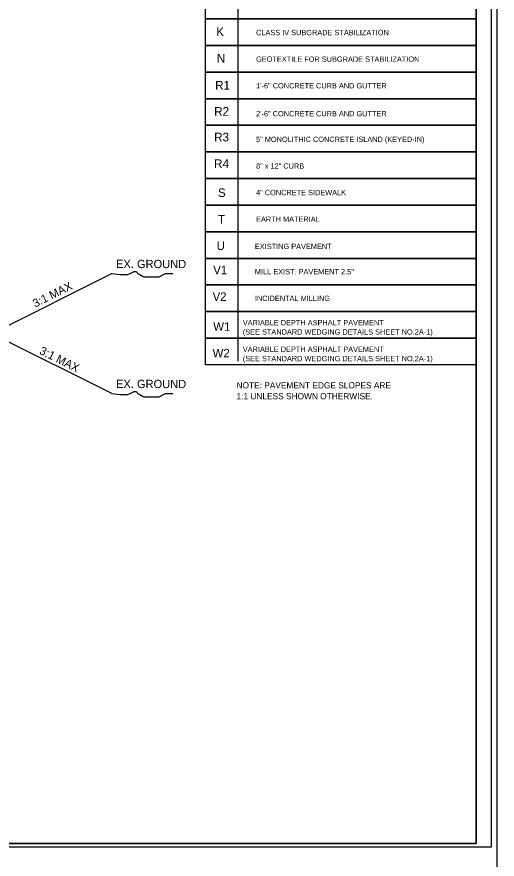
# Model space of a CAD drawing. Extents: x 2320980 to 2456309, y 595047 to 606177.
# Drawn here: x 2455968.3 to 2456045.5, y 596305.6 to 596440.9 of the extents above; entities that cross this region are included whole.
import ezdxf

# ---------------------------------------------------------------- set-up
doc = ezdxf.new("R2010")
doc.units = 0
for name, color, linetype in [('Old_Level_1', 7, 'Continuous'), ('Old_Level_21', 7, 'Continuous'), ('Prop Dimension', 7, 'Continuous'), ('Prop Pavement Schedule Description CELL', 7, 'Continuous'), ('Sheet Plan CELL', 7, 'Continuous'), ('Sheet Plot Border Inside CELL', 7, 'Continuous'), ('Sheet Plot Border Outside CELL', 7, 'Continuous'), ('Typical Slope Point Local CELL', 7, 'Continuous')]:
    doc.layers.add(name, color=color, linetype=linetype)

msp = doc.modelspace()

# ---------------------------------------------------------------- linework, layer by layer
at = {"layer": 'Prop Dimension'}
msp.add_line((2456003.83, 596479.09), (2456003.83, 596385.59), dxfattribs=at)
for points in [[(2455998.64, 596444.88), (2456042.11, 596444.88), (2456042.11, 596440.6), (2455998.64, 596440.6)], [(2455998.64, 596440.6), (2456042.11, 596440.6), (2456042.11, 596436.33), (2455998.64, 596436.33)], [(2455998.64, 596436.33), (2456042.11, 596436.33), (2456042.11, 596432.05), (2455998.64, 596432.05)], [(2455998.64, 596432.05), (2456042.11, 596432.05), (2456042.11, 596427.78), (2455998.64, 596427.78)], [(2455998.64, 596427.78), (2456042.11, 596427.78), (2456042.11, 596423.5), (2455998.64, 596423.5)], [(2455998.64, 596423.5), (2456042.11, 596423.5), (2456042.11, 596419.22), (2455998.64, 596419.22)], [(2455998.64, 596419.22), (2456042.11, 596419.22), (2456042.11, 596414.95), (2455998.64, 596414.95)], [(2455998.64, 596414.95), (2456042.11, 596414.95), (2456042.11, 596410.67), (2455998.64, 596410.67)], [(2455998.64, 596410.67), (2456042.11, 596410.67), (2456042.11, 596406.4), (2455998.64, 596406.4)], [(2455998.64, 596406.4), (2456042.11, 596406.4), (2456042.11, 596402.12), (2455998.64, 596402.12)], [(2455998.64, 596402.12), (2456042.11, 596402.12), (2456042.11, 596397.84), (2455998.64, 596397.84)], [(2455998.64, 596397.84), (2456042.11, 596397.84), (2456042.11, 596393.57), (2455998.64, 596393.57)], [(2455998.64, 596393.57), (2456042.11, 596393.57), (2456042.11, 596389.29), (2455998.64, 596389.29)], [(2455998.64, 596389.29), (2456042.11, 596389.29), (2456042.11, 596385.01), (2455998.64, 596385.01)]]:
    msp.add_lwpolyline(points, close=True, dxfattribs=at)
at = {"layer": 'Prop Pavement Schedule Description CELL'}
msp.add_line((2455998.64, 596385.01), (2455998.64, 596385.01), dxfattribs=at)
at = {"layer": 'Sheet Plan CELL'}
for points in [[(2456042.11, 596518.08), (2455742.1, 596518.08), (2455742.1, 596308.08), (2456042.11, 596308.08)], [(2455742.1, 596308.08), (2455742.1, 596518.07), (2456002.1, 596518.08), (2456002.1, 596488.07), (2456042.11, 596488.06), (2456042.11, 596308.08)]]:
    msp.add_lwpolyline(points, close=True, dxfattribs=at)
at = {"layer": 'Sheet Plot Border Inside CELL'}
msp.add_lwpolyline([(2455711.41, 596307.57), (2456044.6, 596307.58), (2456044.61, 596518.57), (2455711.41, 596518.57)], close=True, dxfattribs=at)
at = {"layer": 'Sheet Plot Border Outside CELL'}
msp.add_lwpolyline([(2455708.81, 596303.57), (2456045.51, 596303.57), (2456045.51, 596522.57), (2455708.81, 596522.57)], close=True, dxfattribs=at)
at = {"layer": 'Typical Slope Point Local CELL'}
for p, q in [((2455964.3, 596390.03), (2455983.59, 596399.68)), ((2455983.59, 596380.39), (2455958.3, 596393.03))]:
    msp.add_line(p, q, dxfattribs=at)
for points in [[(2455983.59, 596399.68), (2455984.97, 596399.5), (2455985.31, 596399.5), (2455985.83, 596399.5), (2455986.17, 596399.5), (2455986.52, 596399.68), (2455986.86, 596399.85), (2455987.21, 596400.02), (2455987.55, 596400.02), (2455987.73, 596399.68), (2455988.07, 596399.5), (2455988.42, 596399.33), (2455988.76, 596399.16), (2455989.11, 596399.16), (2455989.45, 596399.16), (2455989.8, 596399.16), (2455990.14, 596399.16), (2455990.49, 596399.16), (2455990.83, 596399.16), (2455991.18, 596399.16), (2455991.52, 596399.33), (2455991.87, 596399.5), (2455992.21, 596399.68), (2455992.73, 596399.68), (2455993.07, 596399.68), (2455993.42, 596399.68)], [(2455983.59, 596380.39), (2455984.97, 596380.22), (2455985.31, 596380.22), (2455985.83, 596380.22), (2455986.17, 596380.22), (2455986.52, 596380.39), (2455986.86, 596380.56), (2455987.21, 596380.74), (2455987.55, 596380.74), (2455987.73, 596380.39), (2455988.07, 596380.22), (2455988.42, 596380.05), (2455988.76, 596379.87), (2455989.11, 596379.87), (2455989.45, 596379.87), (2455989.8, 596379.87), (2455990.14, 596379.87), (2455990.49, 596379.87), (2455990.83, 596379.87), (2455991.18, 596379.87), (2455991.52, 596380.05), (2455991.87, 596380.22), (2455992.21, 596380.39), (2455992.73, 596380.39), (2455993.07, 596380.39), (2455993.42, 596380.39)]]:
    msp.add_lwpolyline(points, dxfattribs=at)

# ---------------------------------------------------------------- texts
at = {"layer": 'Old_Level_1'}
for p in [(2455984.27, 596400.56), (2455984.27, 596381.28)]:
    msp.add_text('EX. GROUND', height=1.33, rotation=359.9103, dxfattribs=at).set_placement(p)
at = {"layer": 'Old_Level_21'}
for rotation, p in [(26.5659, (2455971.29, 596394.18)), (333.4341, (2455971.84, 596386.84))]:
    msp.add_text('3:1 MAX', height=1.33, rotation=rotation, dxfattribs=at).set_placement(p)
at = {"layer": 'Prop Pavement Schedule Description CELL'}
for s, height, p in [('K', 1.4, (2456000.38, 596437.83)), ('CLASS IV SUBGRADE STABILIZATION', 0.8552, (2456006.77, 596437.98)), ('N', 1.4, (2456000.47, 596433.56)), ('GEOTEXTILE FOR SUBGRADE STABILIZATION', 0.8552, (2456006.77, 596433.7)), ('R1', 1.397, (2456000.2, 596429.24)), ('1\'-6" CONCRETE CURB AND GUTTER', 0.8552, (2456006.77, 596429.43)), ('R2', 1.397, (2456000.04, 596425.03)), ('2\'-6" CONCRETE CURB AND GUTTER', 0.8552, (2456006.77, 596424.94)), ('R3', 1.397, (2456000.04, 596420.91)), ('5" MONOLITHIC CONCRETE ISLAND (KEYED-IN)', 0.8552, (2456006.77, 596420.82)), ('R4', 1.397, (2456000.03, 596416.63)), ('8" x 12" CURB', 0.8552, (2456006.77, 596416.54)), ('S', 1.37, (2456000.66, 596411.99)), ('4" CONCRETE SIDEWALK', 0.8552, (2456006.77, 596412.27)), ('T', 1.37, (2456000.66, 596407.71)), ('EARTH MATERIAL', 0.8552, (2456006.77, 596407.99)), ('U', 1.37, (2456000.44, 596403.47)), ('EXISTING PAVEMENT', 0.8552, (2456006.58, 596403.61)), ('V1', 1.368, (2455999.89, 596399.57)), ('MILL EXIST. PAVEMENT 2.5"', 0.8552, (2456006.58, 596399.55)), ('V2', 1.368, (2455999.79, 596395.29)), ('INCIDENTAL MILLING', 0.8552, (2456006.58, 596395.27)), ('W1', 1.368, (2455999.89, 596390.48)), ('VARIABLE DEPTH ASPHALT PAVEMENT', 0.8552, (2456004.64, 596391.36)), ('(SEE STANDARD WEDGING DETAILS SHEET NO.2A-1)', 0.8552, (2456004.64, 596389.87)), ('W2', 1.368, (2455999.79, 596386.2)), ('VARIABLE DEPTH ASPHALT PAVEMENT', 0.8552, (2456004.64, 596387.09)), ('(SEE STANDARD WEDGING DETAILS SHEET NO.2A-1)', 0.8552, (2456004.64, 596385.59)), ('NOTE: PAVEMENT EDGE SLOPES ARE', 0.9998, (2456003.63, 596381.22)), ('1:1 UNLESS SHOWN OTHERWISE.', 0.9998, (2456003.63, 596379.47))]:
    msp.add_text(s, height=height, dxfattribs=at).set_placement(p)

doc.saveas('drawing.dxf')
